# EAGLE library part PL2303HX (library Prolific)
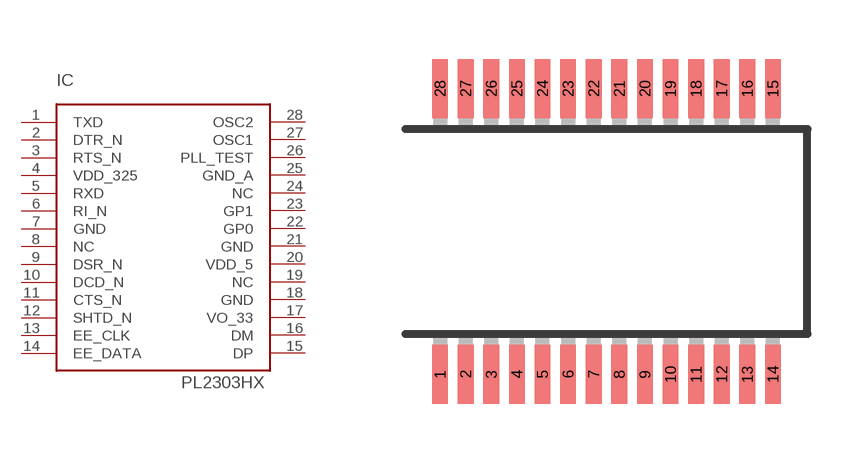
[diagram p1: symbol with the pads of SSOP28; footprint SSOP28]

Designator prefix IC

## PL2303HX  [SSOP28]
1  TXD  out
2  DTR_N  out
3  RTS_N  out
4  VDD_325  pwr
5  RXD  in
6  RI_N
7  GND  pwr
8  NC  nc
9  DSR_N
10  DCD_N
11  CTS_N
12  SHTD_N  out
13  EE_CLK
14  EE_DATA
15  DP
16  DM
17  VO_33  pwr
18  GND  pwr
19  NC  nc
20  VDD_5  pwr
21  GND  pwr
22  GP0
23  GP1
24  NC  nc
25  GND_A  pwr
26  PLL_TEST  in
27  OSC1  in
28  OSC2

## Footprint SSOP28 (pad centres in mm)
smd 0.4 x 1.5: 1 -4.225,-3.625; 2 -3.575,-3.625; 3 -2.925,-3.625; 4 -2.275,-3.625; 5 -1.625,-3.625; 6 -0.975,-3.625; 7 -0.325,-3.625; 8 0.325,-3.625; 9 0.975,-3.625; 10 1.625,-3.625; 11 2.275,-3.625; 12 2.925,-3.625; 13 3.575,-3.625; 14 4.225,-3.625; 15 4.225,3.625; 16 3.575,3.625; 17 2.925,3.625; 18 2.275,3.625; 19 1.625,3.625; 20 0.975,3.625; 21 0.325,3.625; 22 -0.325,3.625; 23 -0.975,3.625; 24 -1.625,3.625; 25 -2.275,3.625; 26 -2.925,3.625; 27 -3.575,3.625; 28 -4.225,3.625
